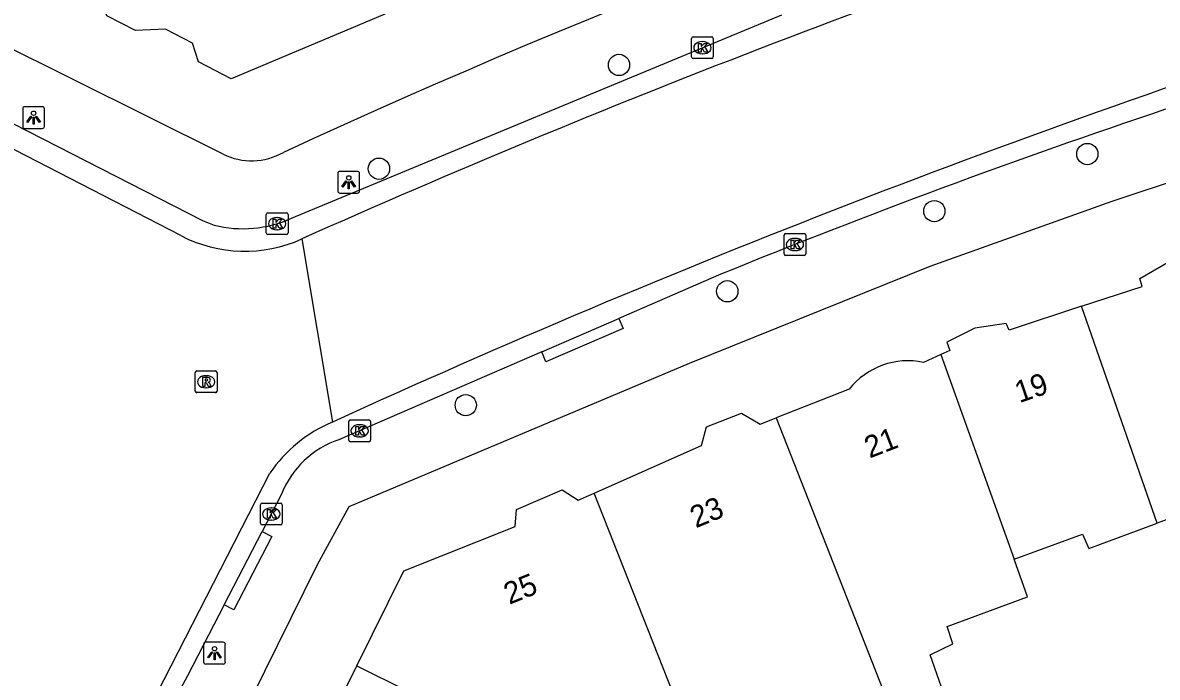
# Model space of a CAD drawing. Extents: x 160356 to 161355, y 381727 to 382845.
# Drawn here: x 161153.1 to 161205.3, y 382329.8 to 382359.9 of the extents above; entities that cross this region are included whole.
import ezdxf

# ---------------------------------------------------------------- set-up
doc = ezdxf.new("R2010")
doc.units = 0
for name, color, linetype in [('IMGEO_Boom', 7, 'Continuous'), ('IMGEO_Kolk', 7, 'Continuous'), ('IMGEO_Lichtpunt', 7, 'Continuous'), ('IMGEO_Pand', 7, 'Continuous'), ('IMGEO_Pand_nummerreeks', 7, 'Continuous'), ('IMGEO_Rijbaan_lokaal_open', 7, 'Continuous'), ('IMGEO_Rioolput', 7, 'Continuous'), ('IMGEO_Voetpad_open', 7, 'Continuous')]:
    doc.layers.add(name, color=color, linetype=linetype)

msp = doc.modelspace()

# ---------------------------------------------------------------- linework, layer by layer
at = {"layer": 'IMGEO_Boom'}
for centre in [(161180.522, 382357.958), (161202.04, 382353.867), (161169.494, 382353.192), (161195.01, 382351.245), (161185.498, 382347.568), (161173.482, 382342.338)]:
    msp.add_circle(centre, 0.489, dxfattribs=at)
at = {"layer": 'IMGEO_Kolk'}
for p, q in [((161183.855, 382358.322), (161183.855, 382359.174)), ((161183.93, 382359.248), (161184.782, 382359.248)), ((161184.856, 382359.174), (161184.856, 382358.322)), ((161184.343, 382359.028), (161184.368, 382359.028)), ((161184.782, 382358.248), (161183.93, 382358.248)), ((161184.366, 382358.468), (161184.341, 382358.468)), ((161164.314, 382350.245), (161164.314, 382351.097)), ((161164.389, 382351.171), (161165.241, 382351.171)), ((161164.802, 382350.951), (161164.827, 382350.951)), ((161165.315, 382351.097), (161165.315, 382350.245)), ((161164.825, 382350.391), (161164.8, 382350.391)), ((161165.241, 382350.171), (161164.389, 382350.171)), ((161188.105, 382349.287), (161188.105, 382350.139)), ((161188.18, 382350.213), (161189.032, 382350.213)), ((161188.593, 382349.993), (161188.618, 382349.993)), ((161189.106, 382350.139), (161189.106, 382349.287)), ((161188.616, 382349.433), (161188.591, 382349.433)), ((161189.032, 382349.213), (161188.18, 382349.213)), ((161168.104, 382340.734), (161168.104, 382341.586)), ((161168.179, 382341.66), (161169.031, 382341.66)), ((161168.592, 382341.44), (161168.617, 382341.44)), ((161169.105, 382341.586), (161169.105, 382340.734)), ((161169.031, 382340.66), (161168.179, 382340.66)), ((161168.615, 382340.88), (161168.59, 382340.88)), ((161164.045, 382336.917), (161164.045, 382337.769)), ((161164.12, 382337.843), (161164.972, 382337.843)), ((161165.046, 382337.769), (161165.046, 382336.917)), ((161164.533, 382337.623), (161164.558, 382337.623)), ((161164.972, 382336.843), (161164.12, 382336.843)), ((161164.556, 382337.063), (161164.531, 382337.063))]:
    msp.add_line(p, q, dxfattribs=at)
for points in [[(161183.855, 382358.322), (161183.855, 382359.174)], [(161183.93, 382359.248), (161184.782, 382359.248)], [(161184.856, 382359.174), (161184.856, 382358.322)], [(161184.176, 382358.948), (161184.299, 382358.948), (161184.299, 382358.797), (161184.429, 382358.948), (161184.593, 382358.948), (161184.447, 382358.797), (161184.6, 382358.548), (161184.448, 382358.548), (161184.363, 382358.712), (161184.299, 382358.645), (161184.299, 382358.548), (161184.176, 382358.548), (161184.176, 382358.948)], [(161184.782, 382358.248), (161183.93, 382358.248)], [(161164.314, 382350.245), (161164.314, 382351.097)], [(161164.389, 382351.171), (161165.241, 382351.171)], [(161164.635, 382350.871), (161164.758, 382350.871), (161164.758, 382350.72), (161164.888, 382350.871), (161165.052, 382350.871), (161164.906, 382350.72), (161165.059, 382350.471), (161164.907, 382350.471), (161164.822, 382350.635), (161164.758, 382350.568), (161164.758, 382350.471), (161164.635, 382350.471), (161164.635, 382350.871)], [(161165.315, 382351.097), (161165.315, 382350.245)], [(161165.241, 382350.171), (161164.389, 382350.171)], [(161188.105, 382349.287), (161188.105, 382350.139)], [(161188.18, 382350.213), (161189.032, 382350.213)], [(161188.426, 382349.913), (161188.549, 382349.913), (161188.549, 382349.762), (161188.679, 382349.913), (161188.843, 382349.913), (161188.697, 382349.762), (161188.85, 382349.513), (161188.698, 382349.513), (161188.613, 382349.677), (161188.549, 382349.61), (161188.549, 382349.513), (161188.426, 382349.513), (161188.426, 382349.913)], [(161189.106, 382350.139), (161189.106, 382349.287)], [(161189.032, 382349.213), (161188.18, 382349.213)], [(161168.104, 382340.734), (161168.104, 382341.586)], [(161168.179, 382341.66), (161169.031, 382341.66)], [(161169.105, 382341.586), (161169.105, 382340.734)], [(161168.425, 382341.36), (161168.548, 382341.36), (161168.548, 382341.209), (161168.678, 382341.36), (161168.842, 382341.36), (161168.696, 382341.209), (161168.849, 382340.96), (161168.697, 382340.96), (161168.612, 382341.124), (161168.548, 382341.057), (161168.548, 382340.96), (161168.425, 382340.96), (161168.425, 382341.36)], [(161169.031, 382340.66), (161168.179, 382340.66)], [(161164.045, 382336.917), (161164.045, 382337.769)], [(161164.12, 382337.843), (161164.972, 382337.843)], [(161165.046, 382337.769), (161165.046, 382336.917)], [(161164.366, 382337.543), (161164.489, 382337.543), (161164.489, 382337.392), (161164.619, 382337.543), (161164.783, 382337.543), (161164.637, 382337.392), (161164.79, 382337.143), (161164.638, 382337.143), (161164.553, 382337.307), (161164.489, 382337.24), (161164.489, 382337.143), (161164.366, 382337.143), (161164.366, 382337.543)], [(161164.972, 382336.843), (161164.12, 382336.843)]]:
    msp.add_lwpolyline(points, dxfattribs=at)
for centre, start, end in [((161183.932, 382359.172), 91.552, 178.448), ((161183.932, 382359.172), 91.552, 178.448), ((161184.78, 382359.172), 1.552, 88.448), ((161184.78, 382359.172), 1.552, 88.448), ((161183.932, 382358.324), 181.552, 268.448), ((161183.932, 382358.324), 181.552, 268.448), ((161184.78, 382358.324), 271.552, 358.448), ((161184.78, 382358.324), 271.552, 358.448), ((161164.391, 382351.095), 91.552, 178.448), ((161164.391, 382351.095), 91.552, 178.448), ((161165.239, 382351.095), 1.552, 88.448), ((161165.239, 382351.095), 1.552, 88.448), ((161164.391, 382350.247), 181.552, 268.448), ((161164.391, 382350.247), 181.552, 268.448), ((161165.239, 382350.247), 271.552, 358.448), ((161165.239, 382350.247), 271.552, 358.448), ((161188.182, 382350.137), 91.552, 178.448), ((161188.182, 382350.137), 91.552, 178.448), ((161189.03, 382350.137), 1.552, 88.448), ((161189.03, 382350.137), 1.552, 88.448), ((161188.182, 382349.289), 181.552, 268.448), ((161188.182, 382349.289), 181.552, 268.448), ((161189.03, 382349.289), 271.552, 358.448), ((161189.03, 382349.289), 271.552, 358.448), ((161168.181, 382341.584), 91.552, 178.448), ((161168.181, 382341.584), 91.552, 178.448), ((161169.029, 382341.584), 1.552, 88.448), ((161169.029, 382341.584), 1.552, 88.448), ((161168.181, 382340.736), 181.552, 268.448), ((161168.181, 382340.736), 181.552, 268.448), ((161169.029, 382340.736), 271.552, 358.448), ((161169.029, 382340.736), 271.552, 358.448), ((161164.122, 382337.767), 91.552, 178.448), ((161164.122, 382337.767), 91.552, 178.448), ((161164.97, 382337.767), 1.552, 88.448), ((161164.97, 382337.767), 1.552, 88.448), ((161164.122, 382336.919), 181.552, 268.448), ((161164.122, 382336.919), 181.552, 268.448), ((161164.97, 382336.919), 271.552, 358.448), ((161164.97, 382336.919), 271.552, 358.448)]:
    msp.add_arc(centre, 0.0765, start, end, dxfattribs=at)
for centre, major_axis, ratio, start_param, end_param in [((161184.342, 382358.748), (-0.387, 0.002), 0.722429, 4.712389, 7.853982), ((161184.367, 382358.748), (-0.39, 0.002), 0.717154, 1.570796, 4.712389), ((161164.801, 382350.671), (-0.387, 0.002), 0.722429, 4.712389, 7.853982), ((161164.826, 382350.671), (-0.39, 0.002), 0.717154, 1.570796, 4.712389), ((161188.592, 382349.713), (-0.387, 0.002), 0.722429, 4.712389, 7.853982), ((161188.617, 382349.713), (-0.39, 0.002), 0.717154, 1.570796, 4.712389), ((161168.591, 382341.16), (-0.387, 0.002), 0.722429, 4.712389, 7.853982), ((161168.616, 382341.16), (-0.39, 0.002), 0.717154, 1.570796, 4.712389), ((161164.532, 382337.343), (-0.387, 0.002), 0.722429, 4.712389, 7.853982), ((161164.557, 382337.343), (-0.39, 0.002), 0.717154, 1.570796, 4.712389)]:
    msp.add_ellipse(centre, major_axis=major_axis, ratio=ratio, start_param=start_param, end_param=end_param, dxfattribs=at)
at = {"layer": 'IMGEO_Lichtpunt'}
for p, q in [((161154.028, 382356.04), (161153.22, 382356.04)), ((161154.028, 382356.04), (161153.22, 382356.04)), ((161153.126, 382355.945), (161153.126, 382355.138)), ((161153.126, 382355.945), (161153.126, 382355.138)), ((161154.122, 382355.138), (161154.122, 382355.945)), ((161154.122, 382355.138), (161154.122, 382355.945)), ((161153.22, 382355.044), (161154.028, 382355.044)), ((161153.22, 382355.044), (161154.028, 382355.044)), ((161167.604, 382352.976), (161167.604, 382352.169)), ((161167.604, 382352.976), (161167.604, 382352.169)), ((161168.506, 382353.071), (161167.698, 382353.071)), ((161168.506, 382353.071), (161167.698, 382353.071)), ((161168.6, 382352.169), (161168.6, 382352.976)), ((161168.6, 382352.169), (161168.6, 382352.976)), ((161167.698, 382352.075), (161168.506, 382352.075)), ((161167.698, 382352.075), (161168.506, 382352.075)), ((161161.439, 382331.357), (161161.439, 382330.55)), ((161161.439, 382331.357), (161161.439, 382330.55)), ((161162.341, 382331.452), (161161.533, 382331.452)), ((161162.341, 382331.452), (161161.533, 382331.452)), ((161162.435, 382330.55), (161162.435, 382331.357)), ((161162.435, 382330.55), (161162.435, 382331.357)), ((161161.533, 382330.456), (161162.341, 382330.456)), ((161161.533, 382330.456), (161162.341, 382330.456))]:
    msp.add_line(p, q, dxfattribs=at)
for points in [[(161153.5, 382355.609), (161153.539, 382355.581), (161153.351, 382355.319), (161153.313, 382355.346), (161153.5, 382355.609)], [(161153.602, 382355.561), (161153.649, 382355.561), (161153.649, 382355.239), (161153.602, 382355.239), (161153.602, 382355.561)], [(161153.712, 382355.581), (161153.75, 382355.608), (161153.937, 382355.346), (161153.898, 382355.318), (161153.712, 382355.581)], [(161167.978, 382352.64), (161168.017, 382352.612), (161167.829, 382352.35), (161167.791, 382352.377), (161167.978, 382352.64)], [(161168.08, 382352.592), (161168.127, 382352.592), (161168.127, 382352.27), (161168.08, 382352.27), (161168.08, 382352.592)], [(161168.19, 382352.612), (161168.228, 382352.639), (161168.415, 382352.377), (161168.376, 382352.349), (161168.19, 382352.612)], [(161161.813, 382331.021), (161161.852, 382330.993), (161161.664, 382330.731), (161161.626, 382330.758), (161161.813, 382331.021)], [(161162.025, 382330.993), (161162.063, 382331.02), (161162.25, 382330.758), (161162.211, 382330.73), (161162.025, 382330.993)], [(161161.915, 382330.973), (161161.962, 382330.973), (161161.962, 382330.651), (161161.915, 382330.651), (161161.915, 382330.973)]]:
    msp.add_lwpolyline(points, dxfattribs=at)
for centre in [(161153.625, 382355.743), (161168.103, 382352.774), (161161.938, 382331.155)]:
    msp.add_circle(centre, 0.0994, dxfattribs=at)
for centre, start, end in [((161153.22, 382355.945), 90, 180), ((161153.22, 382355.945), 90, 180), ((161154.028, 382355.945), 0, 90), ((161154.028, 382355.945), 0, 90), ((161153.22, 382355.138), 180, 270), ((161153.22, 382355.138), 180, 270), ((161154.028, 382355.138), 270, 0), ((161154.028, 382355.138), 270, 360), ((161167.698, 382352.976), 90, 180), ((161167.698, 382352.976), 90, 180), ((161168.506, 382352.976), 0, 90), ((161168.506, 382352.976), 0, 90), ((161167.698, 382352.169), 180, 270), ((161167.698, 382352.169), 180, 270), ((161168.506, 382352.169), 270, 0), ((161168.506, 382352.169), 270, 360), ((161161.533, 382331.357), 90, 180), ((161161.533, 382331.357), 90, 180), ((161162.341, 382331.357), 0, 90), ((161162.341, 382331.357), 0, 90), ((161161.533, 382330.55), 180, 270), ((161161.533, 382330.55), 180, 270), ((161162.341, 382330.55), 270, 0), ((161162.341, 382330.55), 270, 360)]:
    msp.add_arc(centre, 0.0946, start, end, dxfattribs=at)
at = {"layer": 'IMGEO_Pand'}
for points in [[(161170.234, 382360.486), (161162.699, 382357.323), (161161.196, 382358.099), (161160.92, 382358.963), (161159.689, 382359.598), (161158.305, 382359.533), (161156.992, 382360.21), (161156.726, 382361.041), (161156.083, 382361.373)], [(161201.78, 382346.876), (161204.557, 382347.789), (161204.446, 382348.149), (161205.723, 382348.883), (161207.223, 382349.098), (161207.334, 382348.789), (161208.289, 382349.122)], [(161201.78, 382346.876), (161198.445, 382345.78), (161198.314, 382346.08), (161196.875, 382345.877), (161195.589, 382345.234), (161195.73, 382344.844), (161195.316, 382344.66)], [(161205.253, 382336.922), (161201.78, 382346.876)], [(161195.316, 382344.66), (161194.512, 382344.302)], [(161195.316, 382344.66), (161198.675, 382335.265)], [(161191.098, 382343.074), (161187.736, 382341.749)], [(161179.389, 382338.305), (161184.31, 382340.479), (161184.547, 382341.348), (161186.154, 382341.972), (161187.015, 382341.465), (161187.736, 382341.749)], [(161187.736, 382341.749), (161192.48, 382329.718)], [(161168.472, 382330.365), (161170.629, 382334.728), (161175.746, 382336.768), (161175.814, 382337.548), (161177.91, 382338.453), (161178.641, 382337.975), (161179.389, 382338.305)], [(161183.862, 382328.294), (161183.001, 382329.143), (161179.389, 382338.305)], [(161211.989, 382338.038), (161211.628, 382337.92), (161208.251, 382336.819), (161207.868, 382337.888), (161205.253, 382336.922)], [(161198.675, 382335.265), (161201.815, 382336.41), (161202.107, 382335.761), (161205.253, 382336.922)], [(161192.48, 382329.718), (161193.425, 382327.321), (161195.754, 382328.218), (161194.815, 382330.873), (161195.863, 382331.385), (161195.601, 382332.184), (161199.293, 382333.536), (161198.675, 382335.265)], [(161177.936, 382325.564), (161177.763, 382325.494), (161177.488, 382325.63), (161176.279, 382323.184), (161174.062, 382318.701), (161171.826, 382319.807), (161171.529, 382319.207), (161165.287, 382322.293), (161165.641, 382323.008), (161165.029, 382323.31), (161165.34, 382323.939), (161165.061, 382324.762), (161165.963, 382326.586), (161166.733, 382326.847), (161168.472, 382330.365)], [(161168.472, 382330.365), (161177.598, 382325.847), (161177.936, 382325.564)]]:
    msp.add_lwpolyline(points, dxfattribs=at)
msp.add_arc((161193.801, 382340.92), 3.456, 78.1251, 141.4417, dxfattribs=at)
at = {"layer": 'IMGEO_Rijbaan_lokaal_open'}
for points in [[(161160.389, 382350.126), (161143.605, 382358.754), (161144.038, 382359.672)], [(161165.951, 382349.97), (161167.36, 382341.563)], [(161157.045, 382323.157), (161156.387, 382323.442), (161164.48, 382339.209)]]:
    msp.add_lwpolyline(points, dxfattribs=at)
for centre, radius, start, end in [((161343.086, 381952.718), 434.956, 108.03238, 114.03216), ((161348.495, 381944.703), 436.242, 107.75329, 114.53288), ((161163.33, 382355.76), 6.356, 242.4343, 294.3526), ((161169.833, 382335.598), 6.457, 112.5218, 146.0006)]:
    msp.add_arc(centre, radius, start, end, dxfattribs=at)
at = {"layer": 'IMGEO_Rioolput'}
for p, q in [((161161.052, 382342.986), (161161.052, 382343.838)), ((161161.127, 382343.912), (161161.979, 382343.912)), ((161161.54, 382343.692), (161161.565, 382343.692)), ((161162.053, 382343.838), (161162.053, 382342.986)), ((161161.563, 382343.132), (161161.538, 382343.132)), ((161161.979, 382342.912), (161161.127, 382342.912))]:
    msp.add_line(p, q, dxfattribs=at)
for points in [[(161161.052, 382342.986), (161161.052, 382343.838)], [(161161.127, 382343.912), (161161.979, 382343.912)], [(161161.641, 382343.61), (161161.389, 382343.612), (161161.389, 382343.212)], [(161161.567, 382343.531), (161161.513, 382343.531), (161161.513, 382343.45)], [(161162.053, 382343.838), (161162.053, 382342.986)], [(161161.389, 382343.212), (161161.513, 382343.212), (161161.513, 382343.374), (161161.524, 382343.374)], [(161161.513, 382343.45), (161161.565, 382343.45)], [(161161.571, 382343.345), (161161.642, 382343.212), (161161.782, 382343.212), (161161.717, 382343.338)], [(161161.979, 382342.912), (161161.127, 382342.912)]]:
    msp.add_lwpolyline(points, dxfattribs=at)
for centre, radius, start, end in [((161161.129, 382343.836), 0.0765, 91.552, 178.448), ((161161.129, 382343.836), 0.0765, 91.552, 178.448), ((161161.573, 382343.435), 0.0964, 77.0061, 93.1865), ((161161.587, 382343.492), 0.0378, 276.6634, 79.6772), ((161161.64, 382343.5), 0.109, 350.3612, 89.416), ((161161.977, 382343.836), 0.0765, 1.552, 88.448), ((161161.977, 382343.836), 0.0765, 1.552, 88.448), ((161161.129, 382342.988), 0.0765, 181.552, 268.448), ((161161.129, 382342.988), 0.0765, 181.552, 268.448), ((161161.523, 382343.321), 0.0533, 26.0293, 88.6989), ((161161.549, 382343.639), 0.19, 274.7715, 282.9687), ((161161.638, 382343.5), 0.112, 277.5842, 350.9817), ((161161.622, 382343.285), 0.108, 29.5134, 73.7905), ((161161.977, 382342.988), 0.0765, 271.552, 358.448), ((161161.977, 382342.988), 0.0765, 271.552, 358.448)]:
    msp.add_arc(centre, radius, start, end, dxfattribs=at)
for centre, major_axis, ratio, start_param, end_param in [((161161.539, 382343.412), (-0.387, 0.002), 0.722429, 4.712389, 7.853982), ((161161.564, 382343.412), (-0.39, 0.002), 0.717154, 1.570796, 4.712389)]:
    msp.add_ellipse(centre, major_axis=major_axis, ratio=ratio, start_param=start_param, end_param=end_param, dxfattribs=at)
at = {"layer": 'IMGEO_Voetpad_open'}
for points in [[(161162.331, 382353.867), (161144.994, 382362.495)], [(161165.478, 382350.916), (161188.009, 382360.263)], [(161144.038, 382359.672), (161161.391, 382350.814), (161161.921, 382350.6)], [(161223.471, 382358.051), (161213.418, 382355.081), (161203.163, 382351.691), (161194.808, 382348.706), (161183.742, 382344.252), (161168.109, 382337.664), (161166.656, 382335.004), (161159.99, 382321.52)], [(161185.196, 382348.348), (161180.513, 382346.32)], [(161180.513, 382346.32), (161180.708, 382345.861), (161177.166, 382344.326), (161176.971, 382344.785)], [(161176.971, 382344.785), (161180.513, 382346.32)], [(161176.971, 382344.785), (161167.688, 382340.764)], [(161164.997, 382338.218), (161164.126, 382336.535)], [(161164.126, 382336.535), (161164.568, 382336.303), (161162.827, 382332.94), (161162.385, 382333.172)], [(161162.385, 382333.172), (161164.126, 382336.535)], [(161162.385, 382333.172), (161160.695, 382329.907), (161157.045, 382323.157)]]:
    msp.add_lwpolyline(points, dxfattribs=at)
for centre, radius, start, end in [((161313.862, 382031.297), 355.29, 98.98975, 114.75287), ((161314.973, 382029.471), 344.274, 108.51691, 112.14543), ((161163.644, 382356.49), 2.933, 243.4136, 299.7721), ((161163.243, 382355.898), 5.46, 255.9906, 294.163), ((161169.037, 382336.644), 4.336, 108.1222, 158.7058)]:
    msp.add_arc(centre, radius, start, end, dxfattribs=at)

# ---------------------------------------------------------------- texts
at = {"layer": 'IMGEO_Pand_nummerreeks'}
for s, rotation, p in [('19', 18.9248, (161198.917, 382342.428)), ('21', 21.0046, (161192.036, 382339.887)), ('23', 22.4198, (161184.049, 382336.681)), ('25', 22.2141, (161175.484, 382333.168))]:
    msp.add_text(s, height=1, rotation=rotation, dxfattribs=at).set_placement(p)

doc.saveas('drawing.dxf')
